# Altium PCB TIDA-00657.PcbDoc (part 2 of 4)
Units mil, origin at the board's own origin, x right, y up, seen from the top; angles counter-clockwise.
Board outline 2500 x 2500 mil, 4 copper layers (Top Layer, MidLayer1, MidLayer2, Bottom Layer); 149 components, 57 nets, 332 pads, 124 vias.
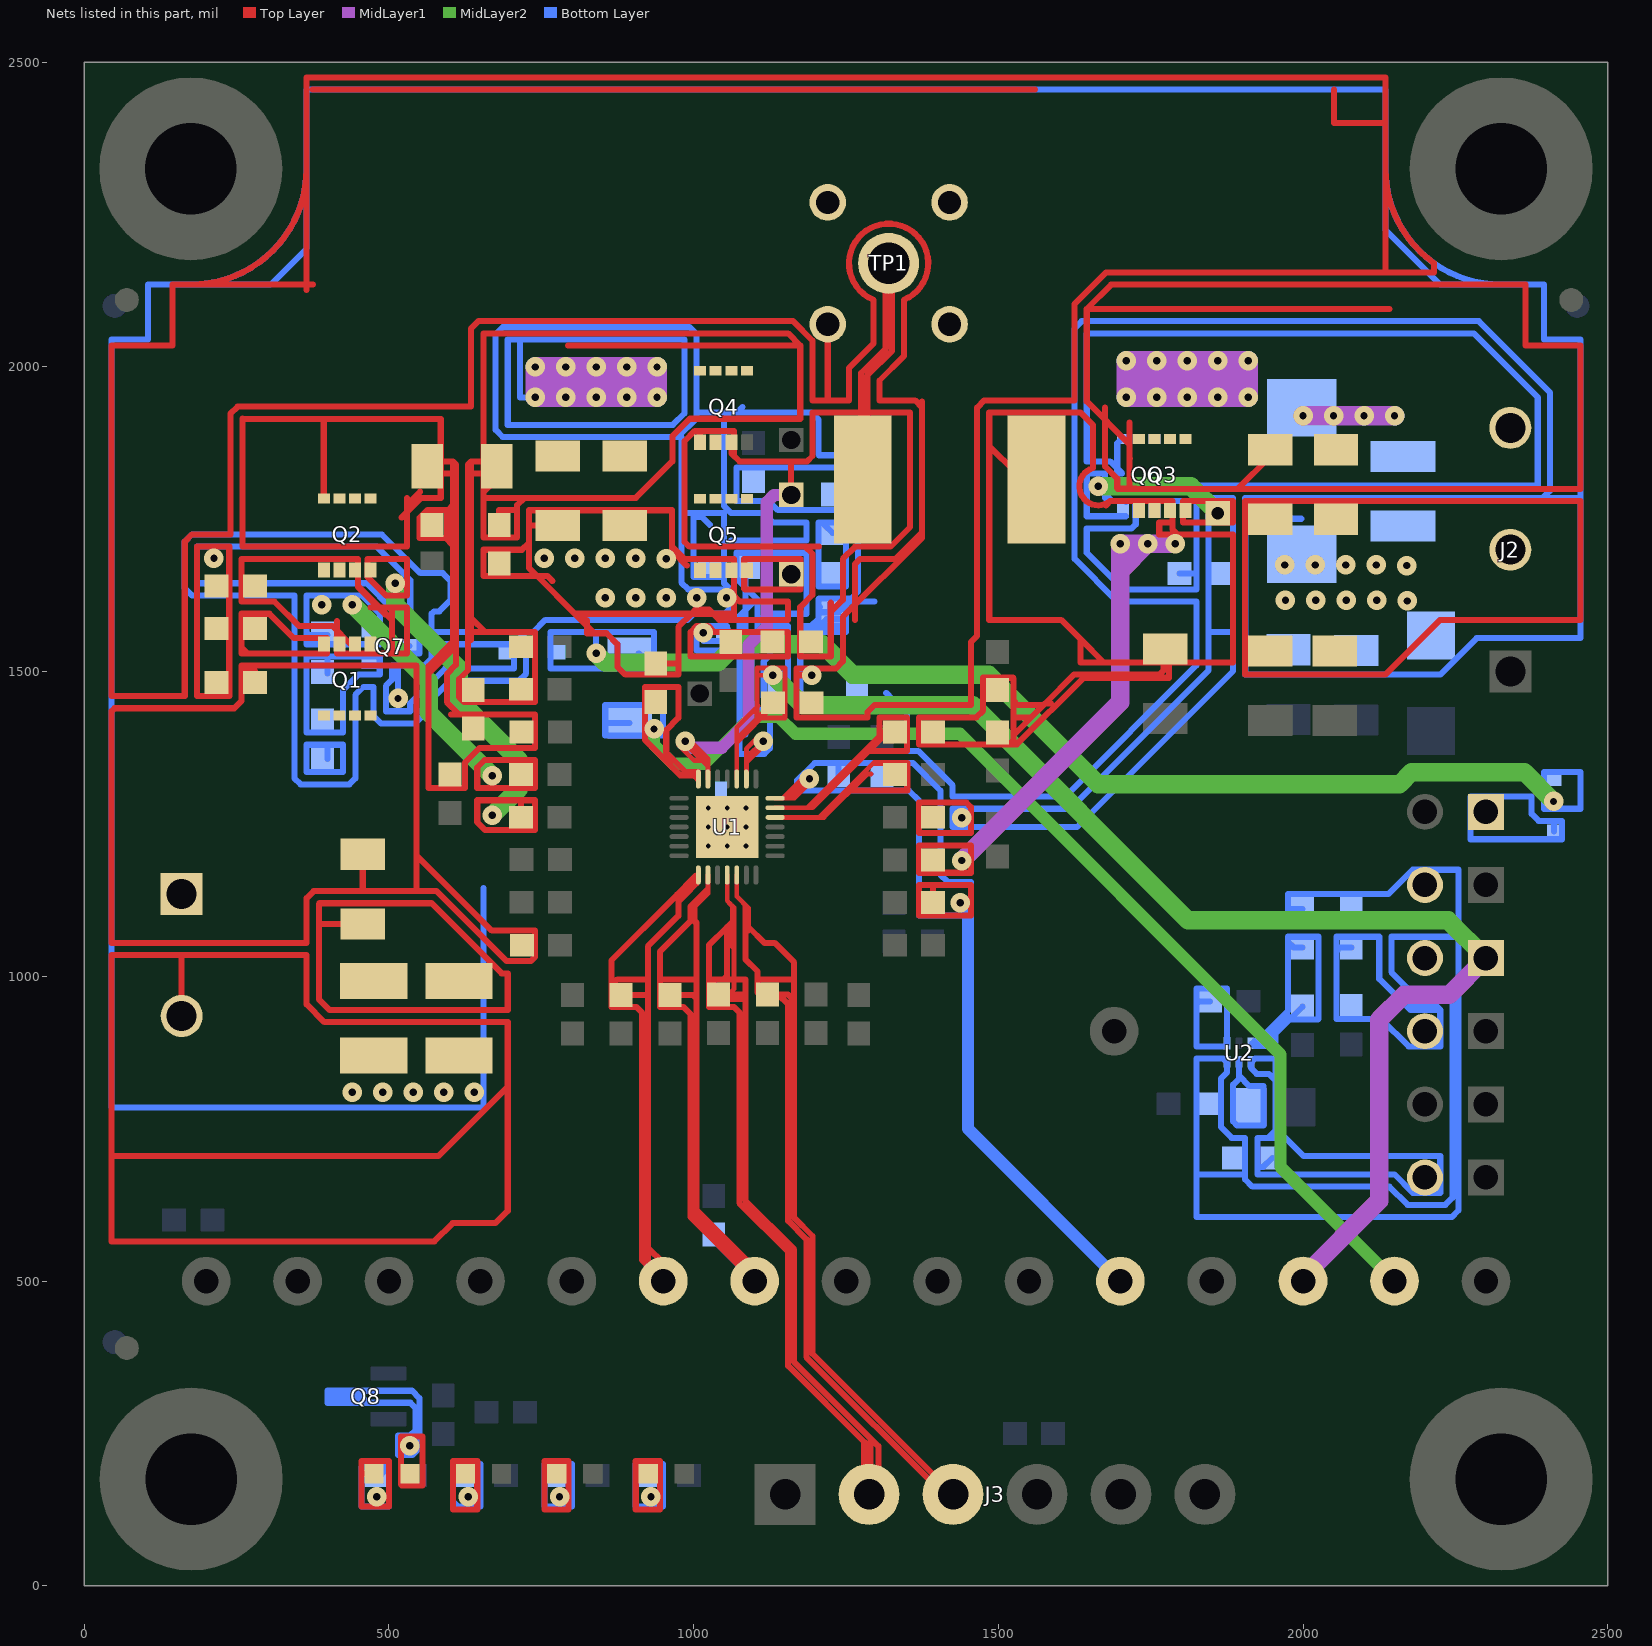
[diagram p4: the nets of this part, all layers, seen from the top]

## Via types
v1: diameter 32, hole 12, Top Layer to Bottom Layer, tented both sides, 115 vias
v2: diameter 19.68, hole 7.87, Top Layer to Bottom Layer, tented both sides, 9 vias

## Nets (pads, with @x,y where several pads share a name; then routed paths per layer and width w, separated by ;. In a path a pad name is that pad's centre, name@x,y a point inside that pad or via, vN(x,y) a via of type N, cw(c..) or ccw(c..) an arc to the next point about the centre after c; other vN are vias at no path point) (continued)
IDCHG: C32.1 TP7.1 U1.8 | length 1808.8
  Top Layer w7.87: U1.8@1004.57,1152.35 U1.8@1004.57,1165.57
  Top Layer w10: C32.1@871.5,969.5 C32.1@881,969.5 ; C32.1@876.5,969.5 C32.1@881,969.5 ; 920.5,969.5 C32.1@881,969.5 ; TP7.1@950.18,529.82 925,555 925,600 ; TP7.1@955.3,505.01 TP7.1@950.18,499.88 ; U1.8@1004.57,1152.35 986.11,1133.89 ; U1.8@1004.57,1165.57 967,1128 ; C32.1@865,950 C32.1@881,966 ; C32.1@865,950 906,950 ; C32.1@865,950 865,985 871,991 875,995 925,995 925,985 ; C32.1@881,966 C32.1@881,969.5 ; C32.1@881,966 897,950 906,950 ; C32.1@881,969.5 865,985.5 865,1026 967,1128 ; 906,950 915,941 915,535.06 TP7.1@950.18,499.88 ; 925,600 925,525.06 TP7.1@950.18,499.88 ; 925,600 925,985 ; 925,985 925,1049.28 975,1099.28 975,1122.78 986.11,1133.89 ; 967,1128 972.89,1133.89 986.11,1133.89
ILIM: C22.2 R10.1 R20.1 R21.2 TP12.1 U1.21 | length 2306.5
  Top Layer w7.87: 1156,1294.43 1185.57,1324 v1(1190,1324) ; v1@1178,1324 1146.31,1292.31 U1.21@1133.74,1292.31 ; U1.21@1133.74,1292.31 1160,1292.31 1190,1322.31 v1(1190,1324) ; U1.21@1133.74,1292.31 1165.31,1292.31 1190,1317 v1(1190,1324)
  Top Layer w10: R10.1@1393,1121 1393,1150 ; 1370,1100 1455,1100 1455,1108 1455,1120 1455,1130 1455,1150 1370,1150 1370,1100
  Bottom Layer w10: C22.2@1238,1330.01 1238,1350 ; 1170,1305 1353,1305 1370,1288 1370,1100 1450,1100 1455,1100 1455,1155 1417,1155 1405,1167 1405,1305 1360,1350 1198.28,1350 1170,1321.72 1170,1305
  Bottom Layer w20: v1(1437.51,1121) 1450,1108.51 1450,1100 1450,750.06 TP12.1@1700.18,499.88
LODRV: C25.1 pad.1@1160,1660 Q5.4 U1.23 | length 1770.4
  Top Layer w7.87: U1.23@1086.5,1323.8 1086.5,1340 ; 1086.5,1358.5 v1(1114,1386) 1114,1378 1086.5,1350.5 1086.5,1340 ; v1@1109.5,1396.5 1086.5,1373.5 1086.5,1340
  Top Layer w10: pad.1@1160,1660 1160,1685 ; 1160,1685 1175,1685 1175,1635 1084,1635 1083,1636 1083,1685 1160,1685
  Bottom Layer w10: 1085,1397 1085,1656 1089.5,1660.5 C25.1@1089.5,1671 C25.1@1089.5,1661.5 ; 1096,1612 1075,1591 1075,1365 1116,1365 1125,1374 1125,1414 ; 1105,1580 1120,1595 1185,1595 1185,1695 1070,1695 1070,1653 1105,1618 1105,1535 1095,1525 1095,1450 1125,1420 1125,1414 ; 1110,1435 1124,1435 1125,1434 1125,1414
NetC1_2: C1.2 R1.2 R2.2 | length 977.2
  Top Layer w10: 385,1085.32 385.84,1086.16 C1.2@457,1086.16 ; R2.2@615,992.02 R2.2@627.98,992.02 ; 385,962.28 385,1119 386,1120 570,1120 685,1005 695,1005 695,945 402.28,945 385,962.28
NetC12_2: C12.2 C13.2 Q2.4 Q7.3 R7.1 R12.2 | length 2669.6
  Top Layer w10: Q2.4@465.18,1662.25 Q2.4@465.18,1655 ; R12.2@717.01,1261.06 717.01,1288.99 ; Q2.4@465.18,1655 495.18,1625 530,1625 530,1685 465.18,1685 Q2.4@465.18,1655 ; 717,1289 740,1289 740,1240 658,1240 645,1253 645,1289 717,1289 ; 185,1460 238,1460 238,1705 185,1705 185,1460
  MidLayer2 w30: v1(510.28,1644.95) 510.28,1609.72 615,1505 615,1453 713,1355 713,1307.76 v1(669.37,1264.13)
  Bottom Layer w10: Q7.3@533.5,1542 505,1542 ; 505,1542 505,1530 550,1530 550,1573 535,1588 535,1650 480,1705 185,1705 185,1645 463.28,1645 505,1603.28 505,1542
  other v1: 213,1686
NetC13_1: C13.1 Q1.1 Q1.2 Q1.3 Q2.1 Q2.2 Q2.3 Q7.2 R6.2 R13.2 | length 2174.2
  Top Layer w10: 415,1530 415,1583.28 ; 416,1530 504,1530 ; 416,1565 416,1548.14 Q1.3@418.82,1545.32 ; Q1.2@436.69,1545.32 407.01,1575 352.28,1575 312.28,1615 258,1615 258,1685 449.02,1685 449.02,1649 ; 470,1605 483,1605 ; 494,1594 483,1605 ; 699,1355 740,1355 740,1309 645,1309 645,1342.72 657.28,1354.99 717.01,1354.99 R13.2@717.01,1331.06 ; 449.02,1649 449.02,1638.98 483,1605 ; 449.02,1649 449.02,1640.98 485,1605 ; 483,1605 485,1605 ; 485,1605 505,1605 ; 485,1605 505,1585 ; 504,1530 505,1531 505,1585 ; 504,1530 530,1530 530,1605 505,1605 ; 505,1585 505,1605
  MidLayer2 w30: v1(440,1610) 565.28,1484.72 565.28,1433.21 v1(669.37,1329.13)
  Bottom Layer w10: 365,1562 366,1563 ; 365.11,1560.11 R6.2@399.07,1560.11 ; 365,1545 365,1624.89 455.11,1624.89 485,1595 485,1545 365,1545
  other v1: 390,1610
NetC16_1: C16.1 C17.1 C18.1 Q2.5 Q2.6 Q2.7 Q2.8 R8.1 R15.2 | length 3395.6
  Top Layer w10: Q2.8@393.16,1784.32 393.16,1914.84 ; 521,1753 553,1785 585,1785 585,1914.84 393.16,1914.84 ; 530,1774 551.16,1795.16 ; 530,1785 530,1705 260,1705 260,1915 260.16,1914.84 393.16,1914.84 ; C17.1@571.54,1740.48 571.54,1719.46 ; 594.46,1719.46 571.54,1719.46 ; 595,1720 595,1765 583,1765 ; 602,1430 740,1430 740,1375 649,1375 625,1351 625,1309 565,1309 565,1497 ; 604,1825 581,1825 569,1837 R8.1@562.91,1837 578,1837 586,1845 605,1845 ; 605,1566 605,1787 ; 610,1555 610,1578 ; 610,1566 610,1609 ; 610,1671 610,1690 ; 610,1702 605,1707 605,1707.28 592.83,1719.46 571.54,1719.46 ; 615,1430 595,1450 595,1496 610,1511 610,1542 ; 565,1497 610,1542 ; 565,1497 565,1509 605,1549 605,1787 ; 571.54,1719.46 550.54,1719.46 550.54,1752.54 563,1765 583,1765 ; 583,1765 597,1765 605,1773 605,1787 ; 605,1787 605,1845 ; 605,1845 610,1840 610,1728 610,1690 ; 610,1542 610,1563 610,1574 610,1578 ; 610,1578 610,1588 610,1601 610,1609 ; 610,1609 610,1690
NetC24_1: C24.1 D2.1 R19.2 | length 731.7
  Top Layer w10: 1041,1565 1033.72,1565 ; R19.2@1061,1549 1049,1561 R19.2@1049,1565 ; 995,1565 1033.72,1565 ; 995,1565 1005,1575 1023.72,1575 1033.72,1565 ; 995,1565 995,1525 1155,1525 1155,1565 R19.2@1049,1565 ; 1033.72,1565 R19.2@1049,1565
  Bottom Layer w10: v1@1005,1559 1005,1571.72 1008.28,1575 1033,1575 ; v1@1016,1550 1052,1550 1055,1547 ; 1033,1575 1015,1575 1005,1565 1005,1535 1055,1535 1055,1575 1033,1575
  other v1: 1016,1564
NetC26_2: C26.2 R25.2 | length 324.9
  Bottom Layer w10: C26.2@1213,1745 1250,1745 1250,1640 1205,1640 1205,1745 1215,1745 1215,1740.5 C26.2@1228,1727.5
NetC27_1: C27.1 pad.0@1860,1760 Q3.4 Q6.4 R28.1 | length 2819.7
  Top Layer w10: 1370,1261 R28.1@1392.99,1261 ; pad.0@1860,1760 1860,1780 ; 1860,1780 1803,1780 1803,1745 1885,1745 1885,1780 1860,1780 ; 1370,1235 1370,1284.99 1447.72,1284.99 1455,1277.72 1455,1235 1370,1235
  MidLayer2 w30: v1(1664,1804) 1816,1804 pad.0@1860,1760
  Bottom Layer w10: v1(1664,1804) 1645,1804 ; 1686.72,1780 1675,1791.72 ; Q6.4@1709,1755 1645,1755 1645,1804 ; 1709.36,1778.7 1708.07,1780 1680,1780 1675,1785 1675,1791.72 ; pad.0@1860,1760 1870,1750 1885,1750 ; 1645,1804 1645,1825 1675,1825 1675,1791.72 ; 1845,1565 1885,1565 ; 1845,1565 1845,1502 1618,1275 1425,1275 1425,1245 1629,1245 1885,1501 1885,1565 ; 1845,1565 1845,1785 1885,1785 1885,1750 ; 1885,1565 1885,1750
  other v1: 1440,1260
NetC27_2: C27.2 C28.1 C29.1 L1.2 Q3.1 Q3.2 Q3.3 Q6.1 Q6.2 Q6.3 R23.1 R26.2 R29.2 | length 4863.2
  Top Layer w10: 1370,1191 R29.2@1393,1191 ; 1370,1193 1372,1195 ; C29.1@1498.5,1469.5 1498.5,1490 ; 1526.5,1397.5 1574,1445 ; L1.2@1528.99,1815.59 1528.99,1826.01 1485,1870 1485,1882 ; 1551,1425 1525,1425 ; 1586.5,1447.5 1576.5,1447.5 ; 1639,1490 1640,1490 ; 1655,1835 1655,1905 1635,1925 1485,1925 1485,1882 ; 1655.13,1833.84 ccw(c1664,1804) 1683.56,1779.78 ; 1676.84,1773 1683.92,1780.08 1706.64,1780.08 1706.72,1780 1756,1780 ; Q3.2@1756.2,1764.34 1756.2,1779.8 1756,1780 ; R23.1@1774,1537.09 1774,1521 R23.1@1780,1515 ; 1485,1882 1485,1585 1603,1585 1635,1553 ; 1498.5,1490 1524,1490 1525,1489 1525,1452 ; 1498.5,1490 1475,1490 1475,1436 1464,1425 1370,1425 1370,1380.5 1517,1380.5 ; 1517,1380.5 1525,1388.5 1525,1425 ; 1517,1380.5 1530.5,1380.5 1640,1490 ; 1525,1425 1525,1452 ; 1525,1452 1532,1445 1574,1445 ; 1574,1445 1576.5,1447.5 ; 1576.5,1447.5 1624,1495 1645,1495 ; 1635,1553 1635,1515 1673,1515 ; 1635,1553 1673,1515 ; 1640,1490 1645,1495 ; 1640,1490 1780,1490 R23.1@1780,1515 ; 1645,1495 1764,1495 1771,1502 R23.1@1771,1515 ; 1673,1515 R23.1@1771,1515 ; 1756,1780 1786,1780 1786,1745 ; R23.1@1771,1515 R23.1@1780,1515 ; R23.1@1780,1515 1885,1515 1885,1725 v1@1794,1725 ; 1786,1745 1786,1733 v1@1794,1725 ; 1786,1745 1764,1745 1764,1725 v1@1794,1725 ; 1370,1170 1455,1170 1455,1215 1370,1215 1370,1170
  MidLayer1 w30: v1(1440,1190) 1700,1450 1700,1665 ; v1(1790,1710) v1(1745,1710) ; 1700,1665 v1(1700,1710) v1(1745,1710) ; 1700,1665 v1(1745,1710)
  Bottom Layer w10: 1725.36,1780 1725.46,1780 ; Q6.3@1729.46,1763.59 Q6.3@1730.2,1764.34 ; C27.2@1797.5,1661 1825,1661 1825,1678 ; 1725.46,1780 1825,1780 1825,1678 ; 1725.46,1780 1725.46,1741.72 1718.73,1735 1645,1735 1645,1695 1705,1635 1825,1635 1825,1678
NetC34_2: C34.2 U2.5 | length 266
  Bottom Layer w10: U2.5@1895,859.84 1895,832 1885.14,822.14 1885.14,761.86 1892,755 1934.43,755 1935,755.57 1935,820 1912,820 1895.31,836.69
NetC35_2: C35.2 JP2.2 R31.1 U2.6 | length 2472.8
  Bottom Layer w10: U2.6@1874.09,859.84 1869.02,864.92 1863.2,864.92 1863.12,865 1825,865 1825,675 ; U2.6@1875.31,859.84 1875.31,842.31 1865,832 1865,753 1883,735 1905,735 1905,666.72 1916.72,655 2141.72,655 2171.72,625 2233.28,625 2245,636.72 2245,957 2227,975 2177,975 2145,1007 2145,1065 2255,1065 2255,616 2244,605 1825,605 1825,675 ; 1905,675 1825,675
NetD1_1: D1.1 D7.1 R17.2 | length 2502.4
  MidLayer2 w30: v1(840,1530) 855,1515 1040,1515 1070,1545 1211,1545 1261,1495 1484,1495 1664,1315 2158,1315 2178,1335 2363,1335 v1(2411,1287)
  Bottom Layer w10: v1(840,1530) 840,1565 ; R17.2@909.91,1530.09 935,1505 ; v1@2397,1290 2395,1288 ; v1(2411,1287) v1@2395,1287 ; 935,1505 935,1565 765,1565 765,1505 935,1505 ; v1@2395,1287 2395,1288 ; v1@2395,1287 2395,1275 2455,1275 2455,1335 2395,1335 2395,1288
NetD1_2: D1.2 JP6.1 | length 450.4
  Bottom Layer w10: D1.2@2412,1237.69 2412,1255 ; 2412,1255 2386.72,1255 2375,1266.72 2375,1295 2275,1295 2275,1225 2425,1225 2425,1255 2412,1255
NetD3_1: D3.1 R44.2 | length 506.8
  Top Layer w10: 455,184 D3.1@475.53,184 ; 455,130 500,130 500,205 455,205 455,130
  Bottom Layer w10: R44.2@479.5,181 486,181 500,195 ; 500,195 500,130 455,130 455,195 500,195
  other v1: 480,146
NetD3_2: D3.2 Q8.3 | length 860.2
  Top Layer w10: D3.2@534.58,184 D3.2@520,184 ; D3.2@520,184 520,166 521,165 555,165 555,245 520,245 D3.2@520,184
  Bottom Layer w10: Q8.3@399,311 Q8.3@424.6,311 454.41,311 465,300.41 ; Q8.3@399,311 399,320 538,320 550,308 550,226 539,215 515,215 515,246.79 535.14,246.79 543.93,255.57 543.93,291.62 535.14,300.41 465,300.41 ; Q8.3@399,311 399,300.82 399.41,300.41 465,300.41
  other v1: 534,230
NetD4_1: D4.1 R42.2 | length 526.8
  Top Layer w10: 755,182 755,205 795,205 795,125 755,125 755,184 D4.1@775.47,184
  Bottom Layer w10: 757,197 755,195 755,130 800,130 800,200 755,200 755,193 767,181 R42.2@779.5,181
  other v1: 780,146
NetD5_1: D5.1 R38.2 | length 505
  Top Layer w10: 605,184 D5.1@625.47,184 ; 605,125 645,125 645,205 605,205 605,125
  Bottom Layer w10: 605,181 R38.2@629.5,181 ; 605,139 614,130 650,130 650,200 613,200 605,192 605,139
  other v1: 630,146
NetD6_1: D6.1 R30.2 | length 528
  Top Layer w10: 905,180 905,205 945,205 945,125 905,125 905,184 D6.1@925.47,184
  Bottom Layer w10: 905,190 905,130 950,130 950,200 905,200 905,181 R30.2@929.5,181
  other v1: 930,146
NetJP1_2: JP1.2 R33.2 R35.2 | length 740.6
  Bottom Layer w10: R33.2@1999,1110.5 1975,1110.5 ; 1975,1110.5 1975,1135 2140,1135 2180,1175 2255,1175 2255,1085 1975,1085 1975,1110.5
NetJP3_2: JP3.2 R35.1 R36.2 | length 751.5
  Bottom Layer w10: 2055,1043 2056,1042 ; 2055,1047.01 2055.5,1047.5 R35.1@2079,1047.5 ; 2147,955 2215,955 2225,945 ; 2225,945 2176,945 2125,996 2125,1065 2055,1065 2055,930 2128,930 2173,885 2225,885 2225,945
NetJP5_2: JP5.2 R31.2 U2.4 | length 1060
  Bottom Layer w10: U2.4@1914.68,859.84 1914.68,849.32 1924,840 1944,840 1955,829 ; U2.4@1915.91,859.84 1921.06,865 1955,865 1955,770 ; 1925,686 1925,735 1940,735 ; R31.2@1949.5,702 1935,687.5 1925.5,687.5 1925,688 1925,675 2150,675 2180,645 2225,645 2225,705 2001,705 1971,735 ; 1940,735 1971,735 ; 1940,735 1942.71,735 1955,747.29 1955,770 ; 1955,770 1955,746.72 1966.72,735 1971,735
NetQ1_4: Q1.4 R7.2 | length 424.8
  Top Layer w10: 258,1540 268,1530 ; R7.2@280.04,1570.66 258.34,1570.66 258,1570.32 ; Q1.4@393.98,1546.07 Q1.4@396,1544.05 ; Q1.4@397,1555 344,1555 304,1595 258,1595 258,1570.32 ; Q1.4@397.98,1555 397.98,1530 268,1530 ; 258,1570.32 258,1530 268,1530
NetQ7_1: Q7.1 R5.2 R6.1 | length 510
  Bottom Layer w10: 392,1525 485,1525 485,1495 450,1495 425,1470 425,1400 365.14,1400 365.07,1400.07 365.07,1524.93 399.07,1524.93 R6.1@399.07,1497.12
NetR32_1: R32.1 U2.1 | length 303.5
  Bottom Layer w10: R32.1@1847.5,959 1830,959 1825,954 ; 1868.94,885 1825,885 1825,954 ; U2.1@1875.31,890.16 1875,890.47 1875,980 1825,980 1825,954
NetR33_1: R33.1 R34.2 U2.3 | length 708.3
  Bottom Layer w10: U2.3@1915.91,890.16 1920.06,886 1934.8,886 ; 1920.75,894 1926,894 1961,929 ; 1952,891 1931,891 1975,935 ; 1955,906.2 1955,887 1954,886 1934.8,886 ; R34.2@1999,950.2 1934.8,886 ; R33.1@1999,1047.5 1984.5,1047.5 1975,1057 ; 1961,929 2024,929 2025,930 2025,1065 1975,1065 1975,1057 ; 1961,929 1975,943 1975,1057
PGND: C2.2 C3.2 C4.2 C5.2 C6.2 C7.2 C8.2 C9.2 C10.2 C11.2 C15.2 C20.2 C21.2 C25.2 D8.2 D9.2 J1.2 J2.2 NT1.2 Q5.1 Q5.2 Q5.3 R1.1 R2.1 R5.1 R25.1 TP1.2 TP1.3 TP1.4 TP1.5 U1.29 | length 34397.1
  Top Layer w10: J1.2@160,935 160,1035 ; 175,2135 ccw(c175,2325) 365,2325 ; 365,2126 365,2475 2135,2475 2135,2155 2144,2155 ; 375,2135 145,2135 145,2035 45,2035 45,1460 165,1460 165,1713.28 176.72,1725 240,1725 240,1923.28 251.72,1935 635,1935 635,2063.28 646.72,2075 1163.28,2075 1195,2043.28 1195,1945 1230,1945 ; 375,2455 1560,2455 ; 768,1649 760,1657 743,1657 ; C3.2@777,1739.83 730.17,1739.83 ; C20.2@938,1513.56 974.56,1513.56 975,1514 975,1530 ; 989,1674 964.83,1698.17 964.83,1714 ; v1@1063,1634 1063,1627.72 1075.72,1615 1155,1615 1155,1585 1066,1585 ; 1065,1595 1032,1595 ; v1(1194,1494) 1168.87,1494 1168.87,1505 ; TP1.3@1220,2070 1220,1945 1230,1945 ; 1265,1585 1265,1676.72 1273.28,1685 1331.28,1685 1375,1728.72 1375,1748 ; 1294.78,2110.09 cw(c1320,2170) 1345.14,2110.06 ; 1295,2110 1295,2038.28 1255,1998.28 1255,1945 1230,1945 ; 1345,2110 1345,2017.72 1305,1977.72 1305,1945 1363.28,1945 1375,1933.28 1375,1906 ; 1375,1943 1375,1906 ; 1905,1750 1905.09,1749.91 C4.2@1946,1749.91 ; 2050.53,2455 2050.53,2400 2133,2400 ; 2135,2325 ccw(c2325,2325) 2215.04,2170.05 ; 2215,2170.02 2215,2155 2144,2155 ; 45,719 45,565 574.72,565 604.72,595 674.72,595 695,615.28 695,833 ; 45,719 45,705 581,705 695,819 695,833 ; 45,719 45,1035 160,1035 ; 160,1035 365,1035 365,954 394,925 695,925 695,833 ; 730.17,1711.89 718.28,1700 655,1700 655,1657 743,1657 ; 730.17,1711.89 730.17,1739.83 ; 730.17,1711.89 730.17,1669.83 743,1657 ; 730.17,1739.83 730.17,1764.83 964.83,1764.83 964.83,1714 ; 743,1657 805,1595 ; 805,1595 996.72,1595 ; 805,1595 815,1585 ; 815,1585 837,1563 ; 815,1585 824,1585 825,1584 825,1563 837,1563 ; 837,1563 857,1563 875,1545 875,1508 888,1495 975,1495 975,1530 ; 964.83,1714 964.83,1704.89 984.72,1685 1066,1685 1066,1585 ; 975,1530 975,1573.28 996.72,1595 ; 996.72,1595 1032,1595 ; 996.72,1595 1003.72,1602 1025,1602 1032,1595 ; 1032,1595 1042,1585 1066,1585 ; 1168.87,1505 1233.28,1505 1245,1516.72 1245,1589.72 1375,1719.72 1375,1748 ; 1168.87,1505 1168.94,1504.94 1168.94,1425 1285,1425 1285,1433.28 1296.72,1445 1455,1445 1455,1548.59 1465,1558.59 1465,1933.28 1476.72,1945 1625,1945 1625,2103.28 1676.72,2155 2144,2155 ; 1375,1748 1375,1906 ; 1905,1495 1905,1780 2455,1780 2455,1585 2224.72,1585 2134.72,1495 1905,1495
  Bottom Layer w10: 175,2135 ccw(c175,2325) 365,2325 ; R5.1@399,1356.5 399,1380 ; v1(640,810) 651,810 655,806 655,797 ; 655,1145 655,797 ; 713.28,1565 725,1553.28 725,1496.72 713.28,1485 600.28,1485 555,1439.72 555,1426.72 543.28,1415 486.72,1415 475,1426.72 475,1475 458.28,1475 445,1461.72 445,1325 435,1315 355,1315 344.89,1325.11 344.89,1625 176.72,1625 165,1636.72 165,1713.28 176.72,1725 488.28,1725 551.64,1661.64 588.36,1661.64 601,1649 601,1617.16 582.84,1599 574,1599 570,1595 570,1565 736.72,1565 756.72,1585 990,1585 1000,1595 1050.72,1595 1065,1609.28 v1@1065,1629.72 ; 982,1760 1000,1760 ; 1000,1754 1013.5,1754 1026.5,1741 ; 1080,1934 1071,1925 ; 1193.28,1575 1205,1586.72 ; 1205,1575 1205,1619 1206,1620 1233,1620 ; 1205,1598 1205.5,1597.5 R25.1@1228,1597.5 1237.5,1597.5 1255,1615 1297,1615 ; 1205,1604 1207,1606 ; 1207,1575 1218,1586 1250,1586 ; 1316,1465 1326,1455 ; 1338.28,1455 1350,1443.28 1350,1370 1368.28,1370 1425,1313.28 1425,1295 1609.72,1295 1825,1510.28 1825,1615 1695,1615 1625,1685 1625,2063.28 1636.72,2075 2288.28,2075 2405,1958.28 2405,1796.72 2393.28,1785 2363,1785 ; 1373,1455 1175,1455 1175,1565 ; 1906,1496 1905,1497 1905,1785 2363,1785 ; 1997,1750.89 1905.11,1750.89 1905.11,1495.11 2225.11,1495.11 2285,1555 2455,1555 2455,2045 2395,2045 2395,2135 2225,2135 2135,2225 2135,2455 365,2455 365,2194 306,2135 105,2135 105,2045 45,2045 45,785 655,785 655,797 ; 2135,2325 ccw(c2325,2325) 2325,2135 ; 2455,1785 2363,1785 ; 974.28,1885 1005,1915.72 1005,1925 ; 974.28,1885 686.72,1885 675,1896.72 675,2053.28 686.72,2065 993.28,2065 1005,2053.28 1005,1925 ; 974.28,1885 980,1885 980,1646 991,1635 1059.72,1635 v1@1065,1629.72 ; 1000,1760 1050,1760 1050,1703.28 ; 1000,1760 1000,1655 1050,1655 1050,1661 ; 1005,1925 1061.72,1925 ; 1050,1661 1050,1644.72 v1@1065,1629.72 ; 1050,1661 1050,1703.28 ; 1050,1703.28 1061.72,1715 1185,1715 1185,1745 1130,1745 1115,1760 1061.72,1760 1050,1771.72 1050,1913.28 1061.72,1925 ; 1061.72,1925 1071,1925 ; 1071,1925 1193.28,1925 1205,1913.28 1205,1856 1206,1855 1258.28,1855 1270,1843.28 1270,1631.72 1258.28,1620 1233,1620 ; 1175,1565 1175,1575 1250,1575 1250,1586 ; 1175,1565 1250,1565 1250,1586 ; 1233,1620 1250,1620 1250,1586 ; 365,1335 425,1335 425,1380 365,1380 365,1335
  other v1: 440,810 490,810 540,810 590,810 2171,1616 1971,1617 2021,1617 2071,1617 2121,1617 855,1621 905,1621 955,1621 1005,1621 1054,1621 2170,1674 1970,1675 2020,1675 2070,1675 2120,1675 955,1685 755,1686 805,1686 855,1686 905,1686
  other v2: 1024,1214.06 1055,1214.06 1086,1214.06 1024,1245.06 1055,1245.06 1086,1245.06 1024,1276.06 1055,1276.06 1086,1276.06
PHASE: C23.2 C24.2 C26.1 L1.1 pad.2@1160,1790 Q4.1 Q4.2 Q4.3 Q5.5 Q5.6 Q5.7 Q5.8 TP1.1 U1.27 | length 3764.8
  Top Layer w7.87: v1@976,1379 1001,1354 1014,1354 ; 1023.38,1343 1023.38,1344.62 1014,1354 ; U1.27@1023.5,1323.8 1023.5,1343 ; v1(986,1386) 995,1386 1023.5,1357.5 1023.5,1343 ; v1(986,1386) 1023.5,1348.5 1023.5,1343 ; v1(986,1386) 986,1382 1014,1354
  Top Layer w10: Q4.1@1010.61,1876.34 1010,1876.95 1010,1895 1002,1895 ; Q4.3@1062.54,1875.59 1062.54,1857.72 1075.27,1845 1152,1845 ; 1066,1854.27 1066,1895 1002,1895 ; pad.2@1160,1790 1160,1845 1152,1845 ; 1206,1705 1171,1705 ; 1225,1613 1225,1594 ; TP1.1@1330,2137 1315,2122 1315,2030 1275,1990 1275,1818.03 L1.1@1277.44,1815.59 1285,1823.16 1285,1986 1325,2026 1325,2130 1330,2135 TP1.1@1330,2170 ; 1002,1895 985,1878 985,1713 993,1705 1171,1705 ; 1152,1845 1186.21,1845 1195,1853.79 1195,1925 1355,1925 1355,1737 1323,1705 1265,1705 1245,1685 1245,1618 1225,1598 1225,1594 ; 1171,1705 1183.28,1705 1195,1693.28 1195,1626 1175,1606 1175,1525 1225,1525 1225,1594
  MidLayer1 w20: v1(986,1386) 997,1375 1046,1375 1090,1419 1090,1543.57 1120,1573.57 1120,1778 1132,1790 pad.2@1160,1790
  Bottom Layer w10: 1070,1780 1123.28,1780 1138.28,1765 1250,1765 1250,1835 1070,1835 1070,1780
PMON: C33.1 R47.1 TP8.1 U1.9 | length 1988.3
  Top Layer w7.87: 994,1100 994,1115 1023.5,1144.5 ; 1002,1087 1002,1114 1023.5,1135.5 U1.9@1023.5,1166.32
  Top Layer w10: 995,619 1100.18,513.82 TP8.1@1100.18,520.82 ; 995,626 995,640 ; 998,1111 995,1114 995,1091 945,1041 945,995 ; 1002,1091 1005,1088 1005,1061 ; 1005,963 998.5,969.5 R47.1@961,969.5 ; 1005,1084 1005,1061 ; TP8.1@1100.18,499.88 1005,595.06 ; TP8.1@1100.18,521 1005,616.18 1005,652 ; R47.1@945,953.5 R47.1@961,969.5 ; R47.1@945,953.5 945,950 983,950 995,938 995,640 ; R47.1@945,953.5 R47.1@945,970 ; R47.1@945,970 946,969 946.5,969.5 R47.1@961,969.5 ; R47.1@945,970 945,995 ; 945,995 1005,995 1005,988 ; 995,640 995,605.06 1005,595.06 ; 1005,595.06 1005,652 ; 1005,652 1005,988 ; 1005,988 1005,1061
  Bottom Layer w10: C33.1@1033,576.5 1033,567.06 TP8.1@1100.18,499.88
REGN: C21.1 D2.2 D9.1 JP2.1 TP14.1 U1.24 | length 2994.9
  Top Layer w7.87: U1.24@1070.75,1323.8 1070.75,1352 ; 1070.75,1372 1070.75,1352 ; 1070.75,1383.75 C21.1@1130.01,1443.01 ; 1070.75,1389.74 1103.94,1422.93 ; 1101,1433 1103.94,1435.94 ; 1106,1424 1150,1424 1149.94,1424.06 1149.94,1506 1103.94,1506 1103.94,1494 ; 1106.01,1444.01 1070.75,1408.75 1070.75,1352 ; C21.1@1130.01,1449 1103.94,1422.93 ; v1(1130,1494) 1103.94,1494 ; 1103.94,1422.93 1103.94,1494
  MidLayer1 w30: TP14.1@2000,500 2000,507 2125,632 2125,929 2165.76,969.76 2239.76,969.76 JP2.1@2300,1030
  MidLayer2 w30: v1(1130,1494) 1179,1445 1458,1445 1811,1092 2238,1092 JP2.1@2300,1030
  Bottom Layer w7.87: 1126.94,1548 1134.31,1548
  Bottom Layer w10: 1125,1549 1126,1548 1134.31,1548 ; 1115,1458.28 1115,1516.72 1125,1526.72 1125,1571.72 1128.28,1575 1155,1575 1155,1455 1118.28,1455 1115,1458.28
SCL: J3.3 R40.2 U1.12 | length 2465
  Top Layer w7.87: U1.12@1070.75,1166.32 1070.75,1131.25 ; 1084,1073 1084,1118 1070.75,1131.25 ; 1090,1074 1090,1112 1070.75,1131.25
  Top Layer w10: 1085,1083.94 1085,1028 1105,1008 1105,995 ; 1090,1081 1116,1055 1133,1055 1165,1023 1165,980 ; 1161,960 1165,960 ; 1185,458 1185,465 ; J3.3@1407,150 J3.3@1425.59,150 1195,380.59 1195,574 1165,604 1165,960 ; J3.3@1410.28,150 1185,375.28 1185,465 ; 1105,995 1105,973.98 1108.99,969.99 R40.2@1121,969.99 R40.2@1139.01,969.99 ; 1105,995 1165,995 1165,980 ; R40.2@1139.01,969.99 1155.01,969.99 1165,960 ; R40.2@1139.01,969.99 1155,954 1155,599 1185,569 1185,465 ; 1165,960 1165,980
SDA: J3.2 R39.1 U1.11 | length 2822
  Top Layer w7.87: 1055,1131 1055,1137 ; U1.11@1055,1166.32 1055,1137 ; 1063,976 1066,979 1066,1113 1059.5,1119.5 ; 1064,1048 1064,1115 1059.5,1119.5 ; 1055,1137 1055,1124 1059.5,1119.5
  Top Layer w10: R39.1@1025,979 1041,979 1025,995 ; R39.1@1025,985.99 R39.1@1041,969.99 ; 1064,1090 1055,1081 ; 1073.01,969.99 R39.1@1041,969.99 ; 1155,428 1155,434 ; 1165,433 1165,444 ; 1025,995 1085,995 1085,948 ; 1025,995 1049,995 1055,1001 1055,1081 ; R39.1@1041,969.99 1081.01,969.99 1085,966 ; R39.1@1041,969.99 1032.99,969.99 1025,962 1025,950 1066,950 1075,941 1075,628 1155.18,547.82 1155.18,476.93 1155,476.75 1155,434 ; 1055,1081 1025,1051 1025,970 1025,963 1082,963 1085,966 ; 1085,948 1085,632 1165,552 1165,444 ; 1085,948 1085,966 ; 1155,434 1155,361 1280,236 1280,157.8 J3.2@1287.8,150 J3.2@1290,152.2 ; 1165,444 1165,367 1290,242 ; J3.2@1290,152.2 1303,165.2 1303,229 1290,242 ; J3.2@1290,152.2 1290,242
SRN: R27.1 U1.19 | length 568.6
  Top Layer w7.87: U1.19@1133.74,1260.81 1156,1260.81 ; 1166.19,1260.81 1156,1260.81 ; 1291,1332 1285,1332 1213.81,1260.81 1192,1260.81 ; 1302,1351 1296,1351 1205.81,1260.81 1192,1260.81 ; 1156,1260.81 1192,1260.81
  Top Layer w10: 1256.22,1305 1350.5,1305 1350.5,1320 ; 1297,1350 1350.5,1350 1350.5,1320 ; R27.1@1330.01,1331 1350.5,1331 1350.5,1320
SRP: R26.1 U1.20 | length 676.4
  Top Layer w7.87: U1.20@1133.74,1276.56 1175,1276.56 ; R26.1@1311,1401 1186.56,1276.56 1175,1276.56 ; R26.1@1330.01,1401 1320,1401 1195.56,1276.56 1175,1276.56
  Top Layer w10: 1289,1370 1350,1370 1350,1377 ; 1305,1389 1305,1425 1350,1425 1350,1377 ; R26.1@1330.01,1401 1350,1401 1350,1377
SYS: C2.1 C3.1 C4.1 C5.1 C10.1 C11.1 C15.1 C16.2 C19.1 J2.3 Q3.5 Q3.6 Q3.7 Q3.8 Q4.5 Q4.6 Q4.7 Q4.8 Q6.5 Q6.6 Q6.7 Q6.8 R8.2 R16.2 | length 10997.7
  Top Layer w10: 630,1593 635,1588 ; 633,1565 688,1565 ; 635,1587.72 657.72,1565 688,1565 ; 638,1825 656,1825 668,1837 R8.2@677.09,1837 662,1837 654,1845 635,1845 ; R8.2@665,1804 655,1794 ; C15.1@681,1740.5 681,1765 710,1765 710,1755 ; 794,2035 1175,2035 ; 1675,1933 1675,1836.84 1695,1816.84 1695,1801 1695.92,1800.08 1725.92,1800.08 1726,1800 ; 1715,1842 1715,1834 ; 1715,1849 1716,1850 ; 1715,1873.28 1645,1943.28 1645,2095 ; 1715,1894.28 1715,1876 ; 1715,1909 1715,1876 ; C4.1@1946,1864.09 1946,1853 1893,1800 1879,1800 ; 2142,2095 1645,2095 ; 2163,1800 2154,1800 ; 630,1546 630,1502.72 615,1487.72 615,1458.28 623.28,1450 740,1450 740,1565 688,1565 ; 630,1546 630,1562 ; 630,1546 630,1552 ; 630,1552 630,1562 ; 630,1552 635,1552 635,1845 ; 630,1562 630,1840 635,1845 ; 655,1785 655,1794 ; 655,1785 655,1720 710,1720 710,1755 ; 655,1785 731.65,1785 ; 655,1794 655,2055 1155,2055 1175,2035 ; 710,1755 710.17,1755.17 710.17,1773.11 721.89,1784.83 731.83,1784.83 731.65,1785 ; 731.65,1785 905,1785 965,1845 965,1886.28 993.72,1915 1175,1915 1175,2035 ; 1645,2095 1685,2135 2365,2135 2365,2035 2455,2035 2455,1800 2154,1800 ; 1715,1834 1715,1800 1726,1800 ; 1715,1834 1715,1876 ; 1726,1800 1879,1800 ; 1879,1800 2154,1800
  MidLayer1 w32: 922,1974 766,1974 v1(740,2000) ; v1(1710,2010) v1(1710,1950) v1(1760,1950) v1(1810,1950) v1(1860,1950) v1(1910,1950) v1(1910,2010) v1(1860,2010) v1(1810,2010) v1(1760,2010) 1711,2010 1741,1980 1751,1980 ; 1735,1964 1751,1980 ; 1898,1980 1751,1980 ; v1(2000,1920) v1(2050,1920) v1(2100,1920) v1(2150,1920) ; v1(740,2000) v1(790,2000) v1(840,2000) v1(890,2000) v1(940,2000) v1(940,1950) v1(890,1950) v1(840,1950) v1(790,1950) v1(740,1950) v1(740,2000)
  Bottom Layer w10: 715,2045 715,1950 v1(740,1950) ; 1703,1825.28 1683.28,1845 1645,1845 1645,2055 2280,2055 2385,1950 2385,1805 1830,1805 1825,1800 1695,1800 1695,1874.72 1703.28,1883 Q6.5@1704.61,1881.66 ; 695,1905 966,1905 985,1924 985,2045 695,2045 695,1905
VCC: C20.1 R17.1 TP17.1 U1.28 | length 2589.3
  Top Layer w7.87: 986,1336 1007.76,1336 U1.28@1007.76,1323.8
  Top Layer w10: C20.1@938,1450.57 932.57,1450.57 920,1438 920,1428 ; 985,1337 955,1367 955,1404 975,1424 975,1475 920,1475 920,1428 ; U1.28@1006.57,1323.8 1000.37,1330 978,1330 920,1388 920,1428
  MidLayer2 w20: v1(935,1406) 935,1380 966,1349 1018,1349 1095,1426 1139,1426 1167,1398 1437,1398 1963,872 1963,687 TP17.1@2150,500
  Bottom Layer w10: R17.1@895,1415.91 856.43,1415.91 855,1417.34 ; 855,1417.34 855,1445 950,1445 950,1395 855,1395 855,1417.34
VIN: C1.1 C12.1 D7.2 J1.1 Q1.5 Q1.6 Q1.7 Q1.8 R3.2 | length 3164.6
  Top Layer w10: C12.1@280.04,1500.66 258.34,1500.66 258,1501 ; 457,1140 C1.1@457,1200.33 ; 545,1199 669,1075 740,1075 740,1032 733,1025 693.28,1025 578.28,1140 545,1140 ; 258,1501 258,1451.72 246.28,1440 50,1440 45,1435 45,1055 365,1055 365,1128.28 376.72,1140 545,1140 ; 258,1501 258,1510 545,1510 545,1140
  Bottom Layer w10: v1(515,1456) 515,1510 558.28,1510 570,1521.72 570,1545 705,1545 705,1505 592,1505 535,1448 535,1435 495,1435 495,1476.72 505,1486.72 505,1510 521,1510
pads on no net: FID1.1 FID2.1 FID3.1 H1.1 H2.1 H3.1 H4.1 H9.0 H10.0 H11.0 H12.0
copper on no net: | length 18.4
  Bottom Layer w32: 1946,1157 1959,1170

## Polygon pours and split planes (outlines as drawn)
GND on Top Layer "Top Layer-No Net" (solid, pour order 18): 360,30 360,360 130,360 130,460 40,460 40,540 1150,540 1150,30 360,30
GND on Top Layer "Bottom Layer-No Net" (solid, pour order 17): 1140,600 1140,30 2140,30 2140,299.35 2141,299.35 2230,398.82 2460,398.82 2460,600 1140,600
GND on Top Layer "Bottom Layer-No Net" (solid, pour order 16): 2460,540 2100,540 2110,550 2110,1220 2190,1220 2210,1200 2460,1200 2460,540
GND on Bottom Layer "Bottom Layer-No Net" (solid, pour order 21): 1640,40 1640,430 1732.25,430 1773.25,470 1773.25,522 1799.9,548 1837.82,548 2460,548 2460,360 2203.75,360 2132,290 2132,40 1640,40
GND on Bottom Layer "Bottom Layer-No Net" (solid, pour order 20): 611,45 611,541 770,700 770,1150 820,1200 1370,1200 1370,1101 1371,1100 1460,1100 1460,720 1640,540 1640,440 1640,40 610,40 610,54
PGND on Bottom Layer "Bottom Layer-No Net" (solid, pour order 19): 40,780 660,780 1430,780 1430,1290 1610,1290 1830,1510 1830,2450 1830,2460 360,2460 360,2200 300,2140 100,2140 100,2050 40,2050 40,780
PGND on MidLayer1 "Bottom Layer-No Net" (solid, pour order 22): 40,440 40,360 200,360 270,360 360,270 360,40 2140,40 2140,200 2140,270 2230,360 2460,360 2460,2140 2300,2140 2230,2140 2140,2230 2140,2460 360,2460 360,2300 360,2230 270,2140 40,2140 40,440
GND on MidLayer2 "MidLayer2-No Net" (solid, pour order 11): 2460,1840 2460,360 2220,360 2140,280 2140,40 360,40 360,270 270,360 40,360 40,2140 270,2140 360,2230 360,2460 690,2460 2140,2460 2140,2230 2230,2140 2460,2140 2460,1840
SYS on MidLayer2 "Bottom Layer-No Net" (solid, pour order 24): 700,1900 700,2450 2140,2450 2140,2300 2140,2230 2230,2140 2411,2140 2460,2140 2460,1850 700,1850 700,1900

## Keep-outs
Keep-Out Layer:
  lines w10: 2500,-5 0,-5 ; 2505,0 2505,2500 ccw(c2500,2500) 2500,2505 0,2505 ccw(c0,2500) -5,2500 -5,0 ; -5,0 ccw(c0,0) 0,-5 ; -5,0 ccw(c0,0) 0,-5 ; -5,0 ccw(c0,0) 0,-5 ; -5,0 ccw(c0,0) 0,-5 ; -5,0 ccw(c0,0) 0,-5 ; -5,0 ccw(c0,0) 0,-5
  text "Keep Out Layer" at 577,-858.49 h60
